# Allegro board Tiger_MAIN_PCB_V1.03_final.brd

Outline 253.3 x 113.9 mm; copper layers: TOP, LAY2, LAY3, LAY4, LAY5, LAY6, LAY7, BOTTOM. Coordinates in mm from the lower left corner of the outline.

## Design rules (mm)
net group +V1.5S: nets +V1.5S AVDD2_AUDIO
net group EDP_TX_DN*: nets EDP_TX_DN*<0> EDP_TX_DN*<1>
net group EDP_TX_DP: nets EDP_TX_DP<0> EDP_TX_DP<1>
net group FLASH_SPI_CLK: nets FLASH_SPI_CLK N26757835
net group FLASH_SPI_D<2>: nets FLASH_SPI_D<2> N26757763
net group FLASH_SPI_D<3>: nets FLASH_SPI_D<3> N26757648
net group FLASH_SPI_MISO: nets FLASH_SPI_MISO N26757791
net group FLASH_SPI_MOSI: nets FLASH_SPI_MOSI N26757807
net group HDA_RST#: nets HDA_RST# N34600535
net group HSON: nets HSON PCIE_RX_DN*<4>
net group HSOP: nets HSOP PCIE_RX_DP<4>
net group I2C_DATA1: nets I2C_DATA1 SMB_L1DATA_PCH
net group LAN_TX0N: nets LAN_TX0N N34595676
net group LAN_TX0P: nets LAN_TX0P N34595663
net group LAN_TX1N: nets LAN_TX1N N34595656
net group LAN_TX1P: nets LAN_TX1P N34595746
net group LAN_TX2N: nets LAN_TX2N N34595569
net group LAN_TX2P: nets LAN_TX2P N34595869
net group LAN_TX3N: nets LAN_TX3N N34595884
net group LAN_TX3P: nets LAN_TX3P N34595477
net group M_B_CLK_DDR<0>: nets M_B_CLK_DDR_DN*<0> M_B_CLK_DDR_DP<0>
net group M_B_CLK_DDR<1>: nets M_B_CLK_DDR_DN*<1> M_B_CLK_DDR_DP<1>
net group M_CLKOUT_SRC_<1>: nets WIFI_PCIE_CLK_DN WIFI_PCIE_CLK_DP
net group M_EDP_AUX_D*: nets EDP_AUX_DN* EDP_AUX_DP
net group M_LAN_PCIE_CLK_D: nets LAN_PCIE_CLK_DN LAN_PCIE_CLK_DP
net group M_LAO1_CLK: nets LAO1_CLKN LAO1_CLKP
net group M_LAO1_DATA0: nets LAO1_DATAN0 LAO1_DATAP0
net group M_LAO1_DATA1: nets LAO1_DATAN1 LAO1_DATAP1
net group M_LAO1_DATA2: nets LAO1_DATAN2 LAO1_DATAP2
net group M_LAO1_DATA3: nets LAO1_DATAN3 LAO1_DATAP3
net group M_LAO_CLK: nets LAO_CLKN LAO_CLKP
net group M_LAO_DATA0: nets LAO_DATAN0 LAO_DATAP0
net group M_LAO_DATA1: nets LAO_DATAN1 LAO_DATAP1
net group M_LAO_DATA2: nets LAO_DATAN2 LAO_DATAP2
net group M_LAO_DATA3: nets LAO_DATAN3 LAO_DATAP3
net group M_MDI0: nets MDI0+ MDI0-
net group M_MDI1: nets MDI1+ MDI1-
net group M_MDI2: nets MDI2+ MDI2-
net group M_MDI3: nets MDI3+ MDI3-
net group M_PCIE_RX_9_SSD: nets PCIE_RX_DN_9_SSD PCIE_RX_DP_9_SSD
net group M_PCIE_RX_10_SSD: nets PCIE_RX_DN_10_SSD PCIE_RX_DP_10_SSD
net group M_PCIE_RX_11_SSD: nets PCIE_RX_DN_11_SSD PCIE_RX_DP_11_SSD
net group M_PCIE_RX_12_SSD: nets PCIE_RX_DN_12_SSD PCIE_RX_DP_12_SSD
net group M_PCIE_RX_12_SSD0: nets N37689443 N37689445
net group M_PCIE_TX_9_SSD: nets PCIE_TX_DN_9_SSD PCIE_TX_DP_9_SSD
net group M_PCIE_TX_9_SSD0: nets N37690406 N37690408
net group M_PCIE_TX_10_SSD: nets PCIE_TX_DN_10_SSD PCIE_TX_DP_10_SSD
net group M_PCIE_TX_10_SSD0: nets N37690460 N37690481
net group M_PCIE_TX_11_SSD: nets PCIE_TX_DN_11_SSD PCIE_TX_DP_11_SSD
net group M_PCIE_TX_11_SSD0: nets N37690514 N37690535
net group M_PCIE_TX_12_SSD: nets PCIE_TX_DN_12_SSD PCIE_TX_DP_12_SSD
net group M_PCIE_TX_12_SSD0: nets N37689471 N37689473
net group M_SSD_PCIE_CLK: nets SSD_PCIE_CLK_DN SSD_PCIE_CLK_DP
net group M_SSD_PCIE_CLK0: nets N37689278 N37689280
net group M_USB2_D22: nets N37310916 N37310979
net group M_USB3_RX_<2>0: nets N37310918 N37310942
net group M_USB3_TX_<2>00: nets N37310944 N37311057
net group MG_FBB_DATA1: nets M_B_DQS_DN*<1> M_B_DQS_DP<1>
net group PCIE_RCOMPN: nets PCIE_RCOMPN PCIE_RCOMPP
net group PCIE_TX_DN*<4>: nets PCIE_TX_C_DN*<4> PCIE_TX_DN*<4>
net group PCIE_TX_DN_1_WIFI: nets PCIE_TX_C_DN_1_WIFI PCIE_TX_DN_1_WIFI
net group PCIE_TX_DP<4>: nets PCIE_TX_C_DP<4> PCIE_TX_DP<4>
net group PCIE_TX_DP_1_WIFI: nets PCIE_TX_C_DP_1_WIFI PCIE_TX_DP_1_WIFI
net group SSD_SATA_RXN1: nets N37458279 SSD_SATA_RXN1
net group SSD_SATA_RXP1: nets N37458304 SSD_SATA_RXP1
net group SSD_SATA_TXN1: nets N37458287 SSD_SATA_TXN1
net group SSD_SATA_TXP1: nets N37458285 SSD_SATA_TXP1
net group USB2_D<10>: nets USB2_DN*<10> USB2_DP<10>
net group USB2_DN*<1>: nets N34544223 USB2_DN*<1>
net group USB2_DN*<4>: nets N37310702 USB2_DN*<4>
net group USB2_DN*<5>: nets N37309832 USB2_DN*<5>
net group USB2_DP<1>: nets N34544176 USB2_DP<1>
net group USB2_DP<4>: nets N37310717 USB2_DP<4>
net group USB2_DP<5>: nets N37309834 USB2_DP<5>
net group USB3_RX_DN*<1>: nets N34544234 USB3_RX_DN*<1>
net group USB3_RX_DP<1>: nets N34544271 USB3_RX_DP<1>
net group USB3_TX_<2>0: nets N37310933 N37310966
net group XDP_BPM: nets XDP_BPM<2> XDP_BPM<3>
net group 50OHM: nets ALL_SYS_PWRGD_VRON CPU_POPIRCOMP CSI2_COMP DRVH1 DRVL1 EC_HID_INT* EC_PCH_RCIN* EDP_BKLEN_OUT EDP_COMP EDP_HPD EDRAM_EDM EDRAM_OPIO_RCOMP EMMC_RCOMP EOPIO_RCOMP EXT_BOOT_STALL_STRAP FAN_VCC ITP_PMODE L_BKLT_EN L_BRIGHTNESS LPC_CLKRUN* LPC_FRAME* MPHY_EXT_PWR_GATE* N26714753 N26739346 N29995527 N30351801 N30362590 N30362889 N30418600 N30418602 N30475256 N30475258 N31079742 N32759666 N32938866 N32938875 N33387416 N33387421 N34176799 NOA_RCOMP PCH_EDM PCH_LPC_CLK1 PCH_PLT_RST* PCH_POPIRCOMP PCH_PWROK PCH_SLP_LAN* PCH_SLP_S5* PCH_SLP_SA* PCH_SLP_WLAN* PCH_SUSACK* PCH_SUSPWRACK* PLT_RST_BUF* PM_CPUPWRGD PM_LANPHY_ENABLE PM_SLP_S3* PM_SUS_STAT* RTC_X1 RTC_X2 SD_RCOMP SM_RCOMP_0 SM_RCOMP_1 SM_RCOMP_2 SOC_CATERR* SOC_THRMTRIP* SW1 TLS_CONFIDENTIALITY WLAN_PCIE_WAKE* XCLK_BIASREF
net group CFG: nets CFG<0> CFG<1> CFG<2> CFG<3> CFG<4> CFG<5> CFG<6> CFG<8> CFG<9> CFG<10> CFG<12> CFG<13>
net group M_DDRB_CMD: nets M_B_A0 M_B_A1 M_B_A2 M_B_A3 M_B_A4 M_B_A5 M_B_A6 M_B_A7 M_B_A8 M_B_A9 M_B_A10 M_B_A11 M_B_A12 M_B_A13 M_B_ACT_N M_B_BG0 M_B_BG1 M_B_BS0 M_B_BS1 M_B_CAS_N M_B_RAS_N M_B_WE_N
net group M_DDRB_CTL_MM: nets M_B_CKE<0> M_B_CKE<1> M_B_CS*<0> M_B_CS*<1> M_B_ODT<0> M_B_ODT<1>
net group M_DDRB_DQS: nets M_B_DQS_DP<0>
net group M_DDRB_DQS0: nets M_B_DQS_DN*<0>
net group M_FLASH_SPI: nets FLASH_SPI_CS*
net group MG_FBB_DATA2: nets M_B_DQ<16> M_B_DQ<17> M_B_DQ<18> M_B_DQ<19> M_B_DQ<20> M_B_DQ<21> M_B_DQ<22> M_B_DQ<23> M_B_DQS_DN*<2> M_B_DQS_DP<2>
net group MG_FBB_DATA3: nets M_B_DQ<24> M_B_DQ<25> M_B_DQ<26> M_B_DQ<27> M_B_DQ<28> M_B_DQ<29> M_B_DQ<30> M_B_DQ<31> M_B_DQS_DN*<3> M_B_DQS_DP<3>
net group MG_FBB_DATA4: nets M_B_DQ<32> M_B_DQ<33> M_B_DQ<34> M_B_DQ<35> M_B_DQ<36> M_B_DQ<37> M_B_DQ<38> M_B_DQ<39> M_B_DQS_DN*<4> M_B_DQS_DP<4>
net group MG_FBB_DATA5: nets M_B_DQ<40> M_B_DQ<41> M_B_DQ<42> M_B_DQ<43> M_B_DQ<44> M_B_DQ<45> M_B_DQ<46> M_B_DQ<47> M_B_DQS_DN*<5> M_B_DQS_DP<5>
net group MG_FBB_DATA6: nets M_B_DQ<48> M_B_DQ<49> M_B_DQ<50> M_B_DQ<51> M_B_DQ<52> M_B_DQ<53> M_B_DQ<54> M_B_DQ<55> M_B_DQS_DN*<6> M_B_DQS_DP<6>
net group MG_FBB_DATA7: nets M_B_DQ<58> M_B_DQ<59> M_B_DQ<60> M_B_DQ<61> M_B_DQ<62> M_B_DQ<63> M_B_DQS_DN*<7> M_B_DQS_DP<7>
net group NET_GND: nets GND
net group PCIE_RX_DN*: nets PCIE_RX_DN_1_WIFI
net group PCIE_RX_DP: nets PCIE_RX_DP_1_WIFI
net group POWER: nets +V1P00A +V1P00S_VCCST +V1P00S_VCCSTG +V1P8A +V1P8A_SIP +V1P8S +V3.3S_MSATA +V3P3_BIOS_SPI +V3P3A +V3P3A_RTC +V3P3A_SIP +V5A +V5S +VCCCORE +VCCDSW_1P0 +VCCGT +VCCPAZIO +VCCPDSW_3P3 +VCCPGPPD +VCCPGPPG +VCCSA +VDDQ_MEM CORE_BOO CORE_FCCM CORE_PWM1 GT_FCCM N36036104 SA_FCCM SA_LG_DRV SA_PWM
net group SMB: nets SMB_CLK SMB_CLK_S2 SMB_DATA SMB_DATA_S2
net group SRC_CLK_REQ*: nets WIFI_CLK_REQ*
net group USB2_DN*: nets USB2_DN*<2> USB2_DN*<3> USB2_DN*<7>
net group USB2_DP: nets USB2_DP<2> USB2_DP<3> USB2_DP<7>
net group USB2_OC*: nets USB2_OC*<0> USB2_OC*<1> USB2_OC*<2> USB2_OC*<3>
net group USB3_RX_DN*: nets USB3_RX_DN*<2>
net group USB3_RX_DP: nets USB3_RX_DP<2>
net group USB3_TX_DN*: nets USB3_TX_DN*<2>
net group USB3_TX_DN*<1>: nets N34544208 N34544244 USB3_TX_DN*<1>
net group USB3_TX_DP: nets USB3_TX_DP<2>
net group USB3_TX_DP<1>: nets N34544097 N34544206 USB3_TX_DP<1>

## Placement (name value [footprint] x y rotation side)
B1  MIC-2_0  [MIC_FOM6050MP3_190P]  57.4 8.1 180 top
C1  20PF  [CC0402N]  207.99 82.8 0 top
C2  20PF  [CC0402N]  206.22 82.8 180 top
C3  1uF  [CC0603N]  177.76 43.69 270 bottom
C4  1uF  [CC0603N]  179.18 43.69 270 bottom
C5  10pF  [CC0402N]  189.22 45.26 0 bottom
C6  10pF  [CC0402N]  187.46 45.26 180 bottom
C7  22nF  [CC0402N]  227.17 44.57 180 bottom
C8  22nF  [CC0402N]  227.17 46.9 180 bottom
C9  100nF  [CC0402N]  196.11 83.57 90 top
C10  100nF  [CC0402N]  195.28 83.57 90 top
C11  100nF  [CC0402N]  196.99 83.57 90 top
C12  100nF  [CC0402N]  197.76 83.56 90 top
C13  0.1u  [CC0402N]  190.59 52.43 0 bottom
C14  10uF  [CC1210N]  159.09 82.19 270 top
C15  47UF  [CC0805N]  192.84 90.81 270 bottom
C16  47UF  [CC0805N]  190.28 89.86 180 bottom
C17  47UF  [CC0805N]  195.91 89.85 180 bottom
C18  47UF  [CC0805N]  205.74 91.34 90 bottom
C19  47UF  [CC0805N]  195.4 95.98 90 bottom
C20  47UF  [CC0805N]  211.32 88.75 90 bottom
C21  47UF  [CC0805N]  209.63 88.76 90 bottom
C22  47UF  [CC0805N]  190.28 91.58 180 bottom
C23  22uF  [CC0603N]  203.66 93.46 90 bottom
C24  22uF  [CC0603N]  209.12 68.71 270 bottom
C25  22uF  [CC0603N]  205.87 68.72 270 bottom
C26  22uF  [CC0603N]  208.17 88.95 90 bottom
C27  22uF  [CC0603N]  197.06 95.78 90 bottom
C28  22uF  [CC0603N]  201.73 86.98 0 top
C29  22uF  [CC0603N]  192.5 88.42 0 bottom
C30  22uF  [CC0603N]  201.73 85.76 0 top
C31  22uF  [CC0603N]  195.57 88.42 180 bottom
C32  10uF  [CC0402N]  206.1 80.49 270 top
C33  10uF  [CC0402N]  208.58 80.49 270 top
C34  10uF  [CC0402N]  204.75 80.49 270 top
C35  10uF  [CC0402N]  201.27 84.75 180 top
C36  10uF  [CC0402N]  201.27 83.94 180 top
C37  10uF  [CC0402N]  201.27 83.06 180 top
C38  10uF  [CC0402N]  203.27 84.82 0 bottom
C39  10uF  [CC0402N]  201.27 84.75 180 bottom
C40  10uF  [CC0402N]  201.27 83.87 180 bottom
C41  10uF  [CC0402N]  201.27 83 180 bottom
C42  10uF  [CC0402N]  203.29 84.75 0 top
C43  10uF  [CC0402N]  203.27 83.93 0 top
C44  10uF  [CC0402N]  203.27 83.02 0 top
C45  10uF  [CC0402N]  203.27 83.02 0 bottom
C46  10uF  [CC0402N]  203.27 83.91 0 bottom
C47  1uF  [CC0201N]  205.37 63.76 90 bottom
C48  1uF  [CC0201N]  206.07 63.75 90 bottom
C49  1uF  [CC0201N]  207.91 63.72 90 bottom
C50  1uF  [CC0201N]  209.66 63.75 90 bottom
C51  1uF  [CC0201N]  208.46 66.25 0 bottom
C52  1uF  [CC0201N]  206.5 66.96 180 bottom
C53  1uF  [CC0201N]  210.43 70.78 270 bottom
C54  1uF  [CC0201N]  209.37 72.63 90 bottom
C55  1uF  [CC0201N]  207.44 72.59 270 bottom
C56  1uF  [CC0201N]  206.61 72.59 270 bottom
C57  1uF  [CC0201N]  205.61 72.59 270 bottom
C58  1uF  [CC0201N]  204.28 70.76 270 bottom
C59  1uF  [CC0201N]  205.29 66.95 0 bottom
C60  1uF  [CC0201N]  209.65 66.87 180 bottom
C61  1uF  [CC0201N]  209.66 65.62 180 bottom
C62  1uF  [CC0201N]  210.27 63.75 90 bottom
C63  1uF  [CC0201N]  205.94 61.58 90 bottom
C64  1uF  [CC0201N]  207.29 61.46 90 bottom
C65  1uF  [CC0201N]  207.13 63.75 90 bottom
C66  1uF  [CC0201N]  208.89 63.75 90 bottom
C67  1uF  [CC0201N]  209.66 66.25 180 bottom
C68  1uF  [CC0201N]  210.18 72.62 90 bottom
C69  1uF  [CC0201N]  208.46 65.61 0 bottom
C70  1uF  [CC0201N]  207.9 61.46 90 bottom
C71  1uF  [CC0201N]  208.42 66.88 0 bottom
C72  1uF  [CC0201N]  206.5 66.25 180 bottom
C73  1uF  [CC0201N]  205.31 66.25 0 bottom
C74  1uF  [CC0201N]  208.81 70.77 270 bottom
C75  1uF  [CC0201N]  207.92 70.76 270 bottom
C76  1uF  [CC0201N]  207.12 70.76 270 bottom
C77  1uF  [CC0201N]  206.2 70.75 270 bottom
C78  1uF  [CC0201N]  205.21 70.74 270 bottom
C79  1uF  [CC0201N]  209.6 70.78 270 bottom
C80  1uF  [CC0201N]  208.35 72.62 90 bottom
C81  1uF  [CC0201N]  204.11 72.84 180 bottom
C82  47UF  [CC0805N]  214.81 87.37 180 top
C83  47UF  [CC0805N]  214.82 89.01 180 top
C84  47UF  [CC0805N]  214.83 85.69 180 top
C85  47UF  [CC0805N]  224.25 88.24 0 top
C86  47UF  [CC0805N]  224.25 89.86 0 top
C87  22uF  [CC0603N]  233.33 70.88 90 top
C88  22uF  [CC0603N]  231.81 70.88 90 top
C89  22uF  [CC0603N]  227.37 88.76 180 bottom
C90  22uF  [CC0603N]  224.46 87.49 0 bottom
C91  22uF  [CC0603N]  227.39 87.49 180 bottom
C92  22uF  [CC0603N]  224.5 90.04 0 bottom
C93  22uF  [CC0603N]  224.46 88.76 0 bottom
C94  10uF  [CC0402N]  220.6 51.93 90 bottom
C95  10uF  [CC0402N]  219.82 51.93 90 bottom
C96  10uF  [CC0402N]  219.04 51.93 90 bottom
C97  10uF  [CC0402N]  238.85 72.92 180 top
C98  10uF  [CC0402N]  238.84 72.13 180 top
C99  10uF  [CC0402N]  238.84 67.36 180 top
C100  10uF  [CC0402N]  238.85 71.35 180 top
C101  10uF  [CC0402N]  231.61 66.52 90 top
C102  10uF  [CC0402N]  236.47 66.46 90 top
C103  10uF  [CC0402N]  218.39 72.87 0 bottom
C104  10uF  [CC0402N]  219.47 70.64 0 bottom
C105  10uF  [CC0402N]  220.19 72.85 180 bottom
C106  1uF  [CC0201N]  221.55 66.18 270 bottom
C107  1uF  [CC0201N]  232.15 65.71 90 bottom
C108  1uF  [CC0201N]  232.87 65.71 90 bottom
C109  1uF  [CC0201N]  231.49 65.71 90 bottom
C110  1uF  [CC0201N]  230.78 65.71 90 bottom
C111  1uF  [CC0201N]  213.34 69.63 90 bottom
C112  1uF  [CC0201N]  225.14 80.97 180 bottom
C113  1uF  [CC0201N]  219.42 69.65 90 bottom
C114  1uF  [CC0201N]  219.43 67.73 90 bottom
C115  1uF  [CC0201N]  212.57 70.85 270 bottom
C116  1uF  [CC0201N]  213.34 70.85 270 bottom
C117  1uF  [CC0201N]  221.54 65 90 bottom
C118  1uF  [CC0201N]  220.72 65 90 bottom
C119  1uF  [CC0201N]  220.73 66.18 270 bottom
C120  10uF  [CC0402N]  236.39 71.33 270 top
C121  10uF  [CC0402N]  235.59 71.33 270 top
C122  10uF  [CC0402N]  234.78 71.33 270 top
C123  10uF  [CC0402N]  212.1 72.84 0 bottom
C124  10uF  [CC0402N]  232.41 66.52 90 top
C125  10uF  [CC0402N]  235.69 66.46 90 top
C126  10uF  [CC0402N]  227.4 89.8 0 bottom
C127  10uF  [CC0402N]  221.76 67.66 270 bottom
C128  10uF  [CC0402N]  217.97 63.71 0 bottom
C129  10uF  [CC0402N]  216.06 63.71 180 bottom
C130  10uF  [CC0402N]  214.16 63.71 0 bottom
C131  10uF  [CC0402N]  212.25 63.71 180 bottom
C132  10uF  [CC0402N]  233.19 66.52 90 top
C133  10uF  [CC0402N]  234.91 66.46 90 top
C134  10uF  [CC0402N]  215.74 72.88 180 bottom
C135  10uF  [CC0402N]  221 67.66 270 bottom
C136  10uF  [CC0402N]  222.21 51.91 90 bottom
C137  10uF  [CC0402N]  221.42 51.92 90 bottom
C138  10uF  [CC0402N]  218.21 51.93 90 bottom
C139  10uF  [CC0402N]  238.84 68.97 180 top
C140  10uF  [CC0402N]  238.84 69.76 180 top
C141  10uF  [CC0402N]  238.84 70.58 180 top
C142  10uF  [CC0402N]  225.15 83.97 0 bottom
C143  10uF  [CC0402N]  217.39 51.93 90 bottom
C144  10uF  [CC0402N]  238.84 68.16 180 top
C145  10uF  [CC0402N]  225.19 81.77 0 bottom
C146  10uF  [CC0402N]  220.29 61.4 180 bottom
C147  10uF  [CC0402N]  218.46 61.43 0 bottom
C148  10uF  [CC0402N]  216.56 61.43 180 bottom
C149  10uF  [CC0402N]  214.65 61.43 0 bottom
C150  1uF  [CC0201N]  231.54 66.86 270 bottom
C151  1uF  [CC0201N]  233.27 71.31 90 bottom
C152  1uF  [CC0201N]  232.65 71.31 90 bottom
C153  1uF  [CC0201N]  232.04 71.31 90 bottom
C154  1uF  [CC0201N]  232.88 66.86 270 bottom
C155  1uF  [CC0201N]  232.16 66.86 270 bottom
C156  1uF  [CC0201N]  217.87 69.63 90 bottom
C157  1uF  [CC0201N]  215.27 69.63 90 bottom
C158  1uF  [CC0201N]  217.08 69.63 90 bottom
C159  1uF  [CC0201N]  216.09 69.63 90 bottom
C160  1uF  [CC0201N]  214.19 69.63 90 bottom
C161  1uF  [CC0201N]  217.84 70.83 270 bottom
C162  1uF  [CC0201N]  217.08 70.83 270 bottom
C163  1uF  [CC0201N]  216.04 70.84 270 bottom
C164  1uF  [CC0201N]  215.28 70.84 270 bottom
C165  1uF  [CC0201N]  214.1 70.85 270 bottom
C166  1uF  [CC0201N]  212.72 69.63 90 bottom
C167  1uF  [CC0201N]  231.43 71.3 90 bottom
C168  1uF  [CC0201N]  230.83 71.3 90 bottom
C169  1uF  [CC0201N]  230.82 66.86 270 bottom
C170  10uF  [CC0402N]  209.06 52.23 0 bottom
C171  10uF  [CC0402N]  198.89 52.31 90 top
C172  10uF  [CC0402N]  205.1 52.35 180 bottom
C173  10uF  [CC0402N]  213.06 52.46 90 top
C174  10uF  [CC0402N]  204.11 52.35 90 top
C175  10uF  [CC0402N]  209.46 52.16 90 top
C176  1uF  [CC0201N]  202.85 61.81 90 bottom
C177  1uF  [CC0201N]  201.96 61.98 90 bottom
C178  1uF  [CC0201N]  202.2 63.47 180 bottom
C179  1uF  [CC0201N]  204.51 61.35 0 bottom
C180  1uF  [CC0201N]  201.09 61.99 90 bottom
C181  1uF  [CC0201N]  210 60.77 180 bottom
C182  1uF  [CC0201N]  204.13 61.96 0 bottom
C183  10uF  [CC0402N]  169.34 56.74 0 top
C184  10uF  [CC0402N]  169.34 57.58 0 top
C185  1uF  [CC0201N]  203.35 52.42 0 bottom
C186  1uF  [CC0201N]  213.29 52.36 0 bottom
C187  22uF  [CC0603N]  216.18 45.29 0 bottom
C188  22uF  [CC0603N]  216.18 43.98 0 bottom
C189  22uF  [CC0603N]  216.18 42.7 0 bottom
C190  1uF  [CC0201N]  203.36 63.29 0 bottom
C191  1uF  [CC0201N]  208.64 60.22 180 bottom
C192  1uF  [CC0201N]  213.29 51.75 0 bottom
C193  10uF  [CC0402N]  170.94 91.63 0 bottom
C194  10uF  [CC0402N]  183.34 85.38 270 bottom
C195  10uF  [CC0402N]  181.65 86.98 180 bottom
C196  10uF  [CC0402N]  181.65 86.05 180 bottom
C197  10uF  [CC0402N]  170.92 89.07 0 bottom
C198  10uF  [CC0402N]  170.94 89.92 0 bottom
C199  47UF  [CC0805N]  178.08 89.62 0 top
C200  1uF  [CC0201N]  208.78 61.74 180 bottom
C201  10uF  [CC0402N]  211.11 61.87 180 bottom
C202  10uF  [CC0402N]  181.65 87.83 180 bottom
C203  10uF  [CC0402N]  180.13 88.84 180 bottom
C204  10uF  [CC0402N]  184.16 85.38 270 bottom
C205  10uF  [CC0402N]  185.37 85.37 270 bottom
C206  10uF  [CC0402N]  186.15 85.38 270 bottom
C207  10uF  [CC0402N]  170.94 90.8 0 bottom
C208  1uF  [CC0402N]  195.92 80.49 270 top
C209  1uF  [CC0201N]  202.86 72.93 0 bottom
C210  1uF  [CC0201N]  200.18 72.95 180 bottom
C211  1uF  [CC0201N]  203.02 68.76 90 bottom
C212  1uF  [CC0201N]  200.58 68.77 90 bottom
C213  1uF  [CC0201N]  203.01 70.62 270 bottom
C214  1uF  [CC0201N]  200.58 70.56 270 bottom
C215  1uF  [CC0201N]  202.64 64.3 0 bottom
C216  1uF  [CC0402N]  198.68 81.16 270 top
C217  1uF  [CC0402N]  213.5 49.96 180 bottom
C218  1uF  [CC0402N]  199.15 72.22 180 bottom
C219  1uF  [CC0402N]  199.57 70.77 90 bottom
C220  1uF  [CC0402N]  182.75 64.4 90 bottom
C221  1uF  [CC0402N]  184.61 50.1 180 bottom
C222  0.1u  [CC0402N]  184.61 51.02 180 bottom
C223  0.1u  [CC0402N]  184.61 51.89 180 bottom
C224  1uF  [CC0402N]  199.42 68.5 270 bottom
C225  1uF  [CC0402N]  178.9 62.33 180 top
C226  1uF  [CC0402N]  170.98 61.79 0 bottom
C227  47UF  [CC0805N]  175.63 71.41 270 bottom
C228  1uF  [CC0402N]  184.01 61.37 180 top
C229  1uF  [CC0402N]  171.02 64.11 0 bottom
C230  1uF  [CC0402N]  184.06 72.03 0 top
C231  1uF  [CC0402N]  184.13 66.81 0 top
C232  1uF  [CC0402N]  176.86 71.2 90 bottom
C233  1uF  [CC0402N]  194.43 52.22 180 bottom
C234  47UF  [CC0805N]  181.85 83.38 90 top
C235  22uF  [CC0603N]  181.9 47.23 180 bottom
C236  22uF  [CC0603N]  181.92 45.97 180 bottom
C237  47UF  [CC0805N]  183.57 83.38 90 top
C238  47UF  [CC0805N]  185.2 83.38 90 top
C239  1uF  [CC0402N]  198.11 69.06 180 bottom
C240  1uF  [CC0402N]  191.86 80.27 270 top
C241  1uF  [CC0402N]  196.36 70.48 270 bottom
C242  47UF  [CC0805N]  180.05 83.39 90 top
C243  47UF  [CC0805N]  175.88 67.34 180 bottom
C244  1uF  [CC0402N]  196.28 52.2 0 bottom
C245  1uF  [CC0402N]  198.34 51.48 90 bottom
C248  100nF  [CC0402N]  168.07 22.71 270 top
C249  2.2uF  [CC0603N]  167.06 22.99 270 top
C250  100nF  [CC0402N]  194 18.11 270 bottom
C264  1000pF  [CC0402N]  104.78 91.14 180 bottom
C274  22nF  [CC0402N]  228.85 49.79 90 top
C281  100nF  [CC0402N]  146.31 85.6 180 bottom
C282  100NF  [CC0402N]  241.24 73.4 270 top
C283  10uF  [CC0603N]  184.83 24.91 270 bottom
C284  0.1u  [CC0402N]  187.14 24.84 270 bottom
C285  100nF  [CC0402N]  76.76 35.61 0 bottom
C286  10uF  [CC0603N]  76.33 54.89 90 bottom
C287  10uF  [CC0805N]  74.26 55.01 270 bottom
C292  100nF  [CC0402N]  77.36 54.88 270 bottom
C293  0.22uF  [CC0603N]  241.19 82.63 270 bottom
C294  0.01uF  [CC0402N]  233.15 95.97 180 bottom
C295  1800PF  [CC0402N]  231.85 93.07 270 bottom
C296  0.1uF  [CC0402N]  231.61 96.98 180 bottom
C297  0.01uF  [CC0402N]  233.15 94.75 180 bottom
C298  10uF  [CC1210N]  98.42 95.77 90 bottom
C299  0.012uF  [CC0603N]  242.53 99.35 0 bottom
C300  68pF  [CC0402N]  232.41 89.12 0 bottom
C301  8200pF  [CC0402N]  231.85 91.19 180 bottom
C302  680pF  [CC0402N]  234.94 85.42 270 top
C303  3900pF  [CC0402N]  242.35 96.45 90 bottom
C304  0.1uF  [CC0402N]  243.64 96.93 0 bottom
C305  0.33 nF  [CC0402N]  237.94 100.92 0 bottom
C306  0.33 nF  [CC0402N]  238.71 83.69 180 top
C307  0.082uF  [CC0603N]  243.14 98.14 180 bottom
C308  270pF  [CC0402N]  232.82 87.33 0 bottom
C309  1.0 nF  [CC0402N]  237.39 98.18 90 bottom
C310  47UF  [CC0805N]  178.59 92.45 0 bottom
C311  0.022uF  [CC0402N]  246.31 84.06 90 bottom
C312  68pF  [CC0402N]  244.94 91.54 0 bottom
C313  8200pF  [CC0402N]  244.94 92.34 0 bottom
C314  470PF  [CC0402N]  240.24 100.44 90 bottom
C315  0.1uF  [CC0402N]  245.84 85.34 0 bottom
C316  330pF  [CC0402N]  236.12 94.14 90 bottom
C317  0.33 nF  [CC0402N]  239.97 94.93 180 bottom
C318  2.2nF  [CC0402N]  246.29 95.96 270 bottom
C319  330pF  [CC0402N]  244.94 93.93 0 bottom
C320  0.01uF  [CC0402N]  244.58 86.71 90 bottom
C321  4.7uF  [CC0603N]  175.78 95.24 180 bottom
C322  220nF  [CC0402N]  89.57 50.84 180 top
C323  4.7uF  [CC0603N]  207.55 95.36 270 bottom
C324  0.33 nF  [CC0402N]  235.46 82.46 180 top
C325  4.7uF  [CC0603N]  158.74 85.32 270 bottom
C326  220nF  [CC0402N]  89.57 50.06 180 top
C327  220nF  [CC0402N]  199.45 80.31 90 top
C328  10uF  [CC0603N]  233.01 39.19 180 bottom
C329  10uF  [CC0603N]  238.28 30.16 0 bottom
C330  220nF  [CC0402N]  200.23 80.31 90 top
C331  220nF  [CC0402N]  202.31 80.26 90 top
C332  220nF  [CC0402N]  201.46 80.25 90 top
C333  220nF  [CC0402N]  89.5 41.67 0 top
C334  0.1u  [CC0402N]  238.24 52.5 90 top
C338  220nF  [CC0402N]  89.5 40.88 0 top
C339  10uF  [CC0603N]  157.56 57.44 0 bottom
C340  0.1u  [CC0402N]  157.46 58.46 0 bottom
C341  0.1u  [CC0402N]  152.36 47.07 180 bottom
C343  10uF  [CC0603N]  152.45 46.06 180 bottom
C344  0.1u  [CC0402N]  162.58 41.82 180 top
C368  0.1uF  [CC0603N]  135.51 18.06 90 bottom
C369  0.1uF  [CC0603N]  136.76 18.06 90 bottom
C371  20PF  [CC0402N]  123.16 34.6 270 bottom
C372  20PF  [CC0402N]  124.35 34.6 270 bottom
C373  0.1u  [CC0402N]  113.32 48.99 90 bottom
C374  0.01uF  [CC0402N]  112.53 44.91 90 bottom
C375  10uF  [CC0805N]  117.98 48.4 90 bottom
C376  10uF  [CC0603N]  112.26 49.03 90 bottom
C377  0.1u  [CC0402N]  130.79 43.46 45 bottom
C378  0.1u  [CC0402N]  131.34 37.4 270 bottom
C379  0.1u  [CC0402N]  125.41 34.66 270 bottom
C380  0.1u  [CC0402N]  127.65 33.67 270 bottom
C381  0.1u  [CC0402N]  121.37 36.65 180 bottom
C382  10uF  [CC0603N]  119.45 48.31 90 bottom
C383  4.7uF  [CC0603N]  132.83 36.82 90 bottom
C384  0.1u  [CC0402N]  121.37 37.45 180 bottom
C385  4.7uF  [CC0603N]  129.83 29.62 90 bottom
C386  0.1u  [CC0402N]  128.97 46.73 225 bottom
C387  0.1u  [CC0402N]  130.86 41.85 45 bottom
C388  0.1u  [CC0402N]  127.46 45.03 45 bottom
C389  0.1u  [CC0402N]  126.57 34.66 270 bottom
C390  0.1u  [CC0402N]  122.27 34.02 270 bottom
C391  0.1u  [CC0402N]  120.71 38.81 180 bottom
C392  0.1u  [CC0402N]  120.69 40.3 180 bottom
C393  0.1u  [CC0402N]  120.79 41.79 180 bottom
C394  0.1u  [CC0402N]  129.72 45.29 225 bottom
C395  0.1u  [CC0402N]  129.18 45.84 225 bottom
C396  1uF  [CC0402N]  128.81 29.79 90 bottom
C397  0.1u  [CC0402N]  122.84 44.95 90 bottom
C398  0.01uF  [CC0402N]  116.5 30.57 90 top
C399  0.1u  [CC0402N]  102.65 30.18 180 top
C400  0.01uF  [CC0402N]  102.64 28.63 0 top
C401  1000pF  [CC1206N]  102.49 27.08 0 top
C402  1000pF  [CC0402N]  102.65 29.4 180 top
C403  0.01uF  [CC0402N]  79.97 18.64 180 top
C404  1000pF  [CC0402N]  79.97 17.84 180 top
C405  10uF  [CC1206N]  26.57 83.42 90 bottom
C406  0.1u  [CC0402N]  25.16 84.28 90 bottom
C407  10uF  [CC1206N]  10.74 90.77 0 bottom
C408  10uF  [CC1206N]  10.71 88.7 0 bottom
C409  1000pF  [CC0402N]  10.77 92.24 180 bottom
C410  0.1u  [CC0402N]  23.77 90.18 90 bottom
C411  100nF  [CC0402N]  19.01 91.04 0 top
C412  100nF  [CC0402N]  19.01 92.04 0 top
C413  100pF  [CC0402N]  30.61 20.09 0 bottom
C414  100pF  [CC0402N]  37.31 20.09 0 bottom
C416  2.2uF  [CC0603N]  192.96 18.55 270 bottom
C417  100nF  [CC0402N]  215.17 14.43 180 bottom
C418  100pF  [CC0402N]  30.04 31 0 top
C419  100pF  [CC0402N]  26.27 25.33 270 top
C421  100pF  [CC0402N]  23.68 25.85 180 top
C422  100pF  [CC0402N]  24.43 27.17 90 top
C424  10uF  [CC0805N]  10.43 31.17 0 bottom
C425  1uF  [CC0603N]  10.53 29.71 180 bottom
C426  10uF  [CC0805N]  4.28 12.87 0 bottom
C427  1uF  [CC0603N]  4.11 11.43 180 bottom
C428  4.7uF  [CC0603N]  9.05 16.84 180 bottom
C429  10uF  [CC0603N]  5.34 25.25 180 bottom
C430  1uF  [CC0603N]  5 26.74 0 bottom
C431  100nF  [CC0402N]  23.18 17.29 180 bottom
C432  100nF  [CC0402N]  8.9 17.86 0 bottom
C433  2.2uF  [CC0603N]  6.28 22.6 90 bottom
C434  10uF  [CC0603N]  8.6 22.27 0 bottom
C435  100nF  [CC0402N]  9.07 21.28 0 bottom
C436  10uF  [CC0603N]  9.05 15.6 180 bottom
C439  100nF  [CC0402N]  8.43 13.15 180 bottom
C440  10uF  [CC0805N]  8.35 11.94 0 bottom
C441  100nF  [CC0402N]  12.15 24.58 270 bottom
C442  10uF  [CC0603N]  11.12 24.97 90 bottom
C443  2.2uF  [CC0603N]  8.48 23.48 180 bottom
C444  10uF  [CC0603N]  8.48 24.69 0 bottom
C445  2.2uF  [CC0603N]  12.93 13.56 90 bottom
C446  2.2uF  [CC0603N]  11.71 13.56 90 bottom
C447  100nF  [CC0402N]  13.57 25.19 180 bottom
C448  10uF  [CC0805N]  13.52 27.37 90 bottom
C449  100nF  [CC0402N]  15.67 25.19 0 bottom
C450  10uF  [CC0805N]  15.48 27.36 90 bottom
C451  10uF  [CC0603N]  18.61 23.85 90 bottom
C452  100nF  [CC0402N]  17.6 23.4 270 bottom
C453  10uF  [CC0603N]  20.11 19.25 180 bottom
C454  100nF  [CC0402N]  19.13 16.81 90 bottom
C455  22pF  [CC0402N]  21.58 20.59 0 bottom
C456  22pF  [CC0402N]  20.45 13.51 180 bottom
C457  22pF  [CC0402N]  21.41 18.19 180 bottom
C458  22pF  [CC0402N]  19.61 20.61 180 bottom
C459  100nF  [CC0402N]  17.34 29.03 0 bottom
C461  2.2uF  [CC0805N]  112.27 27.41 0 top
C463  10uF  [CC0603N]  138.58 31.47 270 bottom
C464  0.1u  [CC0402N]  139.57 38 180 bottom
C469  10uF  [CC0603N]  139.82 39.05 0 bottom
C470  0.01uF  [CC0402N]  136.94 37.98 180 bottom
C477  10uF  [CC0603N]  38.32 57.09 90 bottom
C479  10uF  [CC0603N]  39.64 57.09 90 bottom
C480  0.1u  [CC0402N]  44.2 61.47 180 bottom
C481  1uF  [CC0402N]  62.24 63.94 90 top
C482  10pF  [CC0402N]  63.07 74.53 90 bottom
C483  0.1u  [CC0402N]  63.77 65.83 0 bottom
C484  10pF  [CC0402N]  63.07 72.7 270 bottom
C485  100nF  [CC0402N]  39.66 63.41 180 bottom
C486  0.1u  [CC0402N]  46.53 60.83 180 top
C487  47pF  [CC0402N]  37.93 61.56 90 bottom
C488  10uF  [CC0603N]  125.17 82.18 180 bottom
C489  1uF  [CC0603N]  125.17 83.46 180 bottom
C490  0.01uF  [CC0402N]  129.24 81.08 90 bottom
C491  10uF  [CC0603N]  125.16 86.13 180 bottom
C495  0.1u  [CC0402N]  125.36 87.14 0 bottom
C510  0.1u  [CC0402N]  132.8 81.08 180 top
C511  10uF  [CC0603N]  173.4 26.32 90 bottom
C512  0.1u  [CC0402N]  175.79 27.33 180 bottom
C513  10uF  [CC0603N]  186.12 24.93 270 bottom
C523  10uF  [CC0603N]  177.55 21.83 270 bottom
C535  4.7uF  [CC0603N]  143.86 26.63 180 bottom
C563  10uF  [CC0603N]  147.5 58.4 90 top
C564  0.1u  [CC0402N]  146.23 58.02 90 top
C565  10uF  [CC0603N]  148.96 51.5 90 top
C566  0.1u  [CC0402N]  149.99 51.62 90 top
C603  10uF  [CC1210N]  116.08 88.8 180 bottom
C607  0.1uF  [CC0603N]  121.35 91.2 180 bottom
C608  0.1u  [CC0402N]  159.36 17.75 90 top
C609  0.1u  [CC0402N]  163.64 20.79 0 top
C610  1000pF  [CC0402N]  160.02 14.41 180 top
C633  4.7uF  [CC0603N]  155.77 48.36 270 top
C634  4.7uF  [CC0603N]  158.23 48.37 270 top
C635  4.7uF  [CC0603N]  157.01 48.36 270 top
C640  10uF  [CC0603N]  210.73 16.98 90 bottom
C641  10uF  [CC0603N]  204.82 15.8 270 bottom
C642  10uF  [CC0603N]  196.92 16.07 270 bottom
C643  10uF  [CC0603N]  202.07 17.1 270 bottom
C644  10uF  [CC0603N]  195.71 20.65 90 bottom
C645  10uF  [CC0603N]  201.8 20.52 90 bottom
C646  10uF  [CC0603N]  211.21 20.72 90 bottom
C648  4.7uF  [CC0603N]  27.33 82.32 270 top
C649  4.7uF  [CC0603N]  26.05 82.34 270 top
C650  10uF  [CC0603N]  206.6 20.57 90 bottom
C651  1uF  [CC0402N]  198.56 20.06 90 bottom
C652  1uF  [CC0402N]  209.48 20.31 90 bottom
C653  1uF  [CC0402N]  203.6 20.42 90 bottom
C654  1uF  [CC0402N]  209.03 15.3 270 bottom
C655  1uF  [CC0402N]  207.86 15.56 270 bottom
C656  1uF  [CC0402N]  200.36 16.81 270 bottom
C657  1uF  [CC0402N]  205.21 20.38 90 bottom
C658  1uF  [CC0402N]  203.34 15.89 270 bottom
C659  10uF  [CC0603N]  176.75 10.3 90 top
C660  1000pF  [CC0402N]  64.73 17.41 90 top
C661  100nF  [CC0402N]  58.13 15.47 270 top
C662  100nF  [CC0402N]  174.83 10.58 90 top
C663  100nF  [CC0402N]  175.64 10.58 90 top
C664  100nF  [CC0402N]  173.24 10.58 90 top
C665  100nF  [CC0402N]  174.03 10.58 90 top
C669  470pF  [CC0402N]  243.44 72.39 0 top
C671  4.7uF  [CC0603N]  11.89 83.76 180 top
C673  4.7uF  [CC0603N]  15.57 80.89 270 top
C678  10uF  [CC0603N]  176.14 21.83 270 bottom
C679  1uF  [CC0402N]  174.18 22.01 90 bottom
C680  1uF  [CC0402N]  175 22 90 bottom
C685  1uF  [CC0402N]  171.05 82.74 270 top
C686  1uF  [CC0402N]  170.18 62.7 180 top
C687  0.1u  [CC0402N]  178.74 84.45 270 top
C688  100nF  [CC0402N]  167.9 58.18 90 top
C689  0.01uF  [CC0402N]  167.66 60.62 90 top
C690  1uF  [CC0402N]  169.23 58.4 0 top
C693  0.1uF  [CC0603N]  233.94 34.14 180 bottom
C694  4.7uF  [CC0603N]  238.28 31.75 0 bottom
C695  4.7uF  [CC0603N]  233.94 32.9 180 bottom
C696  1uF  [CC0603N]  242.34 38.92 180 bottom
C697  0.1uF  [CC0603N]  233.5 35.37 180 bottom
C698  0.1u  [CC0402N]  231.75 36.21 90 bottom
C699  10uF  [CC0603N]  233.02 37.91 180 bottom
C700  0.1u  [CC0402N]  159.88 61.6 270 bottom
C701  1uF  [CC0402N]  157.47 59.26 180 bottom
C702  0.01uF  [CC0402N]  157.48 62.24 180 bottom
C703  0.033uF  [CC0603N]  233.93 43.42 270 bottom
C704  0.01uF  [CC0402N]  235.46 42.37 180 bottom
C705  10uF  [CC0603N]  63.15 11.67 0 top
C706  10uF  [CC0603N]  15.63 60.18 270 top
C707  1000pF  [CC0402N]  37.41 92.08 180 bottom
C708  0.01uF  [CC0402N]  21.83 58.51 90 top
C709  1uF  [CC0402N]  160.72 60.82 270 bottom
C710  100nF  [CC0402N]  47.68 92.41 90 bottom
C711  10uF  [CC0603N]  52.03 86.19 270 bottom
C712  1000pF  [CC0402N]  49.11 16.74 270 top
C713  100nF  [CC0402N]  43 22.47 180 top
C714  10uF  [CC0603N]  40.4 16.93 180 top
C715  10uF  [CC0603N]  37.28 91.04 180 bottom
C716  1uF  [CC0402N]  238.6 84.55 0 bottom
C717  680pF  [CC0402N]  235.46 81.68 0 top
C718  330pF  [CC0402N]  247.08 95.96 90 bottom
C719  1.0 nF  [CC0402N]  239.46 100.43 90 bottom
C720  4.7nF  [CC0402N]  231.51 85.57 180 bottom
C721  0.22uF  [CC0603N]  182.41 97.2 0 bottom
C722  68pF  [CC0402N]  238.19 96.34 90 bottom
C723  1UF  [CC0603N]  174.22 97.02 270 top
C724  4.7uF  [CC0603N]  176.14 101.9 90 top
C725  4.7uF  [CC0603N]  174.88 101.9 90 top
C726  10uF  [CC0603N]  40.56 91.06 0 bottom
C727  4.7uF  [CC0603N]  172.36 102.29 90 top
C728  4.7uF  [CC0603N]  173.62 101.91 90 top
C729  10uF  [CC0603N]  48.11 16.55 270 top
C730  4.7uF  [CC0603N]  209.6 103.36 90 bottom
C731  4.7uF  [CC0603N]  210.81 103.37 90 bottom
C732  1UF  [CC0603N]  213.25 102.75 90 top
C733  4.7uF  [CC0603N]  215.24 102.62 0 top
C734  4.7uF  [CC0603N]  215.25 101.35 0 top
C735  1UF  [CC0603N]  161.3 83.05 270 top
C736  4.7uF  [CC0603N]  158.81 83.05 270 top
C737  4.7uF  [CC0603N]  160.08 83.05 270 top
C738  0.22uF  [CC0603N]  214.02 96.83 180 bottom
C739  10uF  [CC0603N]  46.89 16.57 270 top
C740  0.22uF  [CC0603N]  163.36 90.94 270 bottom
C741  10uF  [CC0603N]  63.66 17.27 90 top
C742  10uF  [CC0603N]  63.66 14.52 270 top
C746  0.1u  [CC0402N]  172.79 48.09 270 top
C747  0.1u  [CC0402N]  171.99 48.08 270 top
C758  1uF  [CC0402N]  159.78 46.88 0 top
C759  0.1uF  [CC0402N]  166.35 70.81 90 top
C761  1uF  [CC0402N]  167.17 45.39 180 top
C767  0.1u  [CC0402N]  18.79 71.83 270 bottom
C768  2.2uF  [CC0603N]  13.57 60.54 270 top
C770  0.1u  [CC0402N]  24.94 67.66 0 bottom
C771  0.1u  [CC0402N]  14.59 60.42 270 top
C772  0.1u  [CC0402N]  32.64 74.25 0 top
C773  1uF  [CC0603N]  16.99 75.71 270 bottom
C774  1uF  [CC0603N]  17.48 67.49 270 bottom
C775  0.1uF  [CC0603N]  15.18 75.68 270 bottom
C776  1UF  [CC0603N]  21.29 64.26 90 bottom
C777  2.2uF  [CC0603N]  32.77 73.12 0 top
C778  0.1u  [CC0402N]  27.12 70.99 0 bottom
C779  0.1u  [CC0402N]  23.11 67.65 180 bottom
C780  0.1u  [CC0402N]  12.92 71.81 90 bottom
C781  0.1u  [CC0402N]  26.58 69.56 90 bottom
C782  4.7uF  [CC0603N]  143.88 27.85 180 bottom
C784  0.1uF  [CC0603N]  141.88 14.03 270 bottom
C785  0.1uF  [CC0603N]  141.88 16.77 270 bottom
C786  0.1uF  [CC0603N]  143.87 25.4 0 bottom
C787  0.1uF  [CC0603N]  138.09 18.09 90 bottom
C790  0.01uF  [CC0402N]  28.56 61.1 270 top
C791  10uF  [CC0805N]  32.58 71.66 180 top
C792  10uF  [CC0603N]  29.91 58.74 90 top
C793  0.01uF  [CC0402N]  34.09 79.54 180 top
C794  0.01uF  [CC0402N]  31 58.77 270 top
C795  0.01uF  [CC0402N]  27.77 78.83 270 top
C796  10uF  [CC0805N]  33.88 78.32 180 top
C797  10uF  [CC0603N]  23.68 57.2 270 top
C802  0.01uF  [CC0402N]  21.66 62.68 180 top
C803  10uF  [CC0603N]  20.65 58.45 270 top
C804  0.1u  [CC0402N]  164.75 42.02 270 top
C805  0.1u  [CC0402N]  159.22 48.22 270 top
C806  3900pF  [CC0402N]  244.36 83.76 90 bottom
C807  100nF  [CC0402N]  170.54 79.82 0 top
C808  100nF  [CC0402N]  175.47 81.53 225 top
C942  0.1u  [CC0402N]  125.36 87.94 0 bottom
C992  2.2uF  [CC0603N]  128.9 85.11 0 top
C2762  100nF  [CC0402N]  43.18 89.37 0 top
C2763  100nF  [CC0402N]  43.19 90.32 0 top
C2764  100nF  [CC0402N]  140.2 89.63 270 top
C2765  100nF  [CC0402N]  135.02 85.21 0 bottom
C2766  10uF  [CC0603N]  146.45 79.75 0 bottom
C2767  10uF  [CC0603N]  142.59 76.58 90 bottom
C2768  0.01uF  [CC0402N]  142.33 79.14 180 bottom
C2769  2.2uF  [CC0603N]  146.49 81.95 180 bottom
C2770  1uF  [CC0402N]  146.18 80.9 180 bottom
C2771  100nF  [CC0402N]  142.33 78.37 180 bottom
C2772  0.01uF  [CC0402N]  146.32 83.99 180 top
C2773  100nF  [CC0402N]  146.32 84.81 180 top
C2774  1uF  [CC0402N]  146.31 84.8 180 bottom
C2775  0.01uF  [CC0402N]  136.33 31.7 90 bottom
C2776  10uF  [CC0603N]  137.35 31.47 90 bottom
C2777  100nF  [CC0402N]  135.49 31.71 90 bottom
C2778  10uF  [CC0603N]  129.6 8.49 180 top
C2779  100nF  [CC0402N]  129.91 10.41 0 top
C2780  100nF  [CC0402N]  129.92 9.56 0 top
C2781  4.7uF  [CC0603N]  76.25 101.8 90 bottom
C2782  0.1u  [CC0402N]  75.26 101.32 90 bottom
C2783  0.1u  [CC0402N]  71.53 101.29 270 bottom
C2784  0.1u  [CC0402N]  78.17 98.75 0 bottom
C2785  1uF  [CC0402N]  70.88 99.15 270 bottom
C2786  0.1u  [CC0402N]  73.63 100.79 180 bottom
C2787  4.7uF  [CC0603N]  78.44 101.11 0 bottom
C2788  0.1u  [CC0402N]  77.83 96.36 180 bottom
C2789  2.2uF  [CC0603N]  78.11 95.36 0 bottom
C2790  4.7uF  [CC0603N]  78.44 99.75 0 bottom
C2791  4.7uF  [CC1206N]  94.39 98.08 90 bottom
C2833  10uF  [CC5750N]  98.46 95.78 90 bottom
C2834  470nF  [CC0402N]  129.71 86.71 90 top
C2835  10uF  [CC1210N]  120.64 88.79 0 bottom
C2836  10uF  [CC0805N]  96.57 57.57 180 bottom
C2837  10uF  [CC0805N]  96.56 59.21 0 bottom
C2838  0.1u  [CC0402N]  96.88 55.07 0 bottom
C2839  1uF  [CC0603N]  96.89 56.1 180 bottom
C2840  0.01uF  [CC0402N]  105.63 72.47 180 top
C2841  0.01uF  [CC0402N]  105.63 71.7 180 top
C2842  0.01uF  [CC0402N]  104.01 78.88 270 top
C2843  0.01uF  [CC0402N]  104.8 78.88 270 top
C2844  2.2uF  [CC0603N]  14.45 13.5 90 bottom
C2845  2.2uF  [CC0603N]  15.66 13.5 90 bottom
C2846  100nF  [CC0402N]  146.31 83.06 180 bottom
C2847  100nF  [CC0402N]  146.31 83.83 0 bottom
C2848  100nF  [CC0402N]  146.31 88.1 0 bottom
C2849  100nF  [CC0402N]  146.31 87.34 0 bottom
C2850  100nF  [CC0402N]  146.31 86.36 180 bottom
C2852  47UF  [CC0805N]  178.59 90.83 0 bottom
C2853  4.7uF  [CC0603N]  169.3 98.07 180 bottom
C2854  4.7uF  [CC0603N]  169.3 96.85 180 bottom
CN1  1782A1BX52A  [SMD-DDR4-50X820P-260N-AR]  205.99 17.89 0 top
CN3  SAF-0001BX-41-5N-0XX  [SMD-SATA-127P-22AN-L-KX]  100.47 62.94 270 top
CN5  213MAAA32  [SMD-M2PCIE-50X750P-75BN]  83.11 43.92 270 top
CN7  BS-06-A3A0J001  [SMD-BATTERY-2900P-2N]  71.96 85.15 0 bottom
CN9  CDZ-1.7-V10-2010  [TH-DCIN-540P-3N]  116.39 20.6 270 top
CN10  RJB-2X08X-XX-XX-XXX  [TH-RJ45-127P-8N]  95.04 20.6 90 top
CN14  1.25T-2-2PWB-T  [SMD-CN-125P-2WBN]  3.07 12.13 270 top
CN16  F2T20U-XXT3-E  [SMD-CN-50P-20N-H]  71.63 63.16 0 top
CN21  1.25T-2-2PWB-T  [SMD-CN-125P-2WBN]  247.52 26.52 90 top
CN22  SHNG04X-XX-XX-XXX  [TH-USB-250PX200P-4BN]  53.21 20.65 90 top
CN23  SHNG04X-XX-XX-XXX  [TH-USB-250PX200P-4BN]  68.93 20.65 90 top
CN24  CN-USB-9+4  [SMD-USB-100P-9AN]  35.85 95.1 180 top
CN25  WB1012US-04T5  [SMD-CN-100P-4N-V-CB]  167.15 16.19 90 top
CN26  M.2 SOCKET-1 SD/DP KEY E  [SMD-M2PCIE-50X750P-75AN]  128 22.61 90 top
CN35  WB1003UR-40XXB  [SMD-CN-100P-40AN-H]  135.37 99.5 180 bottom
CN36  CN-USB-9+4  [SMD-USB-100P-9AN]  8.95 95.1 180 top
CN37  MC38-1200X-XXD  [SMD-SD-250P-9N]  70.6 97.25 180 top
CN41  WB2012DR-02T2  [TH-CN-200P-2N-H]  92.3 93.69 180 bottom
CN42  WB1012US-02T5  [SMD-CN-100P-2N-V-CB]  57.99 7.82 0 top
CP1  220uF  [CCP7343N]  204.16 90.11 0 top
CP2  220uF  [CCP7343N]  200.49 94.83 90 bottom
CP3  220uF  [CCP7343N]  242.43 100.45 0 top
CP4  220uF  [CCP7343N]  241.68 90.13 0 top
CP7  330uF  [CCP7343N]  246.28 53.24 90 top
CP8  220uF  [CCP7343N]  178.67 91.82 0 bottom
CP9  330uF  [CCP7343N]  241.22 53.23 90 top
CP10  47UF  [CAE630W570HN]  216.58 101.89 0 bottom
CP13  330uF  [CCP7343N]  163.43 70.7 90 top
CP14  150UF  [CAE630W570HN]  7.66 62.49 180 top
CP15  150UF  [CAE630W570HN]  29.12 67.27 0 top
CP18  220uF  [CCP7343N]  242.43 95.28 0 top
CP20  330uF  [CCP7343N]  38.79 86.33 180 bottom
CP50  10UF  [THR-CPR50-630X1100N]  101.56 95.81 28.8 top
CP51  47UF  [CAE630W570HN]  168.94 97.49 180 bottom
CP52  220uF  [CCP7343N]  167.86 97.6 180 bottom
D1  BAT54WS-7-F  [SOD1713N]  172.46 45.24 90 top
D6  SK34L  [SOD5225N]  123.9 18.34 270 bottom
D7  AOZ8231  [SOD0806N]  9.88 91.52 0 top
D8  AOZ8231  [SOD0806N]  8.08 91.52 180 top
D17  1SS355TE17  [SOD2514N]  145.2 15.84 90 bottom
D18  1SS355TE17  [SOD2514N]  161.2 15.82 0 top
D19  AOZ8231  [SOD0806N]  64.51 19.62 270 top
D20  AOZ8231  [SOD0806N]  64.51 21.52 90 top
D21  AOZ8231  [SOD0806N]  48.92 19.58 270 top
D22  AOZ8231  [SOD0806N]  48.92 21.48 90 top
D23  SK34L  [SOD5225N]  18.44 80.72 90 top
D24  D_2PN  [SOT95P280-3N]  24.01 70.04 180 bottom
D25  D_2PN  [SOT95P280-3N]  23.61 65.04 90 bottom
D26  BAT54WS-7-F  [SOD1713N]  157.13 43.71 0 top
D28  SK34L  [SOD5225N]  7.81 79.03 90 top
D29  1SS355TE17  [SOD2514N]  147.19 15.84 90 bottom
D30  BAT54WS-7-F  [SOD1713N]  86.71 77.06 270 bottom
D31  BAT54WS-7-F  [SOD1713N]  88.43 77.06 270 bottom
D38  B2100  [SOD5336N]  106.7 94.02 180 bottom
D42  DFLS1100-7  [SOD2818N]  106.42 93.98 180 bottom
D2512  AOZ8231  [SOD0806N]  34.9 91.82 180 top
D2513  AOZ8231  [SOD0806N]  36.81 91.81 0 top
F2  1206L110//NANOSMDC110F  [F1206N]  22.25 85.98 180 bottom
F3  1206L110//NANOSMDC110F  [F1206N]  48.95 87.54 180 bottom
F4  1206L110//NANOSMDC110F  [F1206N]  41.8 18.78 0 top
F5  1206L110//NANOSMDC110F  [F1206N]  61.8 14.68 90 top
F8  3216FF-5A  [F1206N]  128.05 21.66 180 bottom
F9  0.5A  [F1206N]  118.57 84.48 270 bottom
FB2  120  [FB0805N]  78.65 55.08 90 bottom
FB3  120  [FB0805N]  72.08 51.58 270 bottom
FB4  120  [FB0805N]  133.03 20.28 180 bottom
FB5  120  [FB0805N]  133.03 21.91 180 bottom
FB6  47  [FB0603N]  79.91 22.14 0 top
FB7  120.0 ohm  [FB0603N]  11.69 27.69 90 bottom
FB8  120.0 ohm  [FB0603N]  6.53 10.07 180 bottom
FB9  120.0 ohm  [FB0603N]  5.34 28.21 180 bottom
FB10  120.0 ohm  [FB0603N]  22.92 15.52 90 bottom
FB11  120.0 ohm  [FB0603N]  8.61 26.69 90 bottom
FB12  120.0 ohm  [FB0603N]  9.87 26.68 90 bottom
FB13  180ohm  [FB0603N]  19.85 23.84 270 bottom
FB14  120  [FB0805N]  4.52 19.26 0 bottom
FB15  120  [FB0805N]  138.65 35.42 90 bottom
FB16  180  [FB0603N]  40.27 59.71 0 bottom
FB17  47  [FB0603N]  79.9 20.91 0 top
FB18  47  [FB0603N]  79.89 19.68 0 top
FB19  220  [FB0603N]  78.43 102.42 0 bottom
FB20  220  [FB0603N]  80.87 95.36 0 bottom
FB21  180  [FB0603N]  163.6 21.87 180 top
FB22  120.0 ohm  [FB0603N]  170.88 100.31 180 top
FB23  120.0 ohm  [FB0603N]  170.88 99.09 180 top
FB24  120.0 ohm  [FB0603N]  211.99 102.22 90 top
FB25  120.0 ohm  [FB0603N]  208.68 99.32 180 bottom
FB26  120.0 ohm  [FB0603N]  156.95 85.35 0 top
FB37  180  [FB0603N]  141.91 87.46 180 top
FB38  180  [FB0603N]  145.86 82.18 270 top
FB39  180  [FB0603N]  147.87 76.96 270 bottom
FB40  120  [FB0805N]  96.53 61.08 180 bottom
FB44  180  [FB0603N]  142 89.25 180 top
FB45  180  [FB0603N]  149.18 78.46 90 bottom
FIL1  330mA  [FIL_175P200X120-4L]  101.61 32.51 270 top
FIL2  330mA  [FIL_175P200X120-4L]  101.47 35.55 270 top
FIL3  330mA  [FIL_175P200X120-4L]  104.62 38.45 90 bottom
FIL4  330mA  [FIL_175P200X120-4L]  104.59 41.46 90 bottom
FIL5  330mA  [FIL_175P200X120-4L]  8.98 89.63 180 top
FIL6  330mA  [FIL_175P200X120-4L]  5.86 89.91 180 top
FIL7  330mA  [FIL_175P200X120-4L]  16.74 91.54 270 top
FIL9  330mA  [FIL_175P200X120-4L]  46.95 20.52 270 top
FIL10  330mA  [FIL_175P200X120-4L]  62.54 20.57 90 top
FIL14  330mA  [FIL_175P200X120-4L]  40.81 89.82 270 top
FIL15  330mA  [FIL_175P200X120-4L]  35.86 89.9 180 top
FIL16  330mA  [FIL_175P200X120-4L]  32.87 89.64 180 top
J2  PJ-358A  [TH-EARPHONE-330X400P-5N]  32.54 15.61 0 top
J3  PJ-358A  [TH-EARPHONE-330X400P-5N]  32.54 26.7 0 top
J5  CSI-1182-06XX-CN  [SMD-CN-100P-6N-H]  93.62 87.18 180 bottom
L3  2.2uH  [LC3030DL]  132.35 32.12 270 bottom
L4  2.2uH  [LC6666N]  9.07 70.96 270 top
L5  1.0uH  [LC6666N]  247.1 43.38 90 top
L9  2.2uH  [LC3030DL]  145.1 76.58 90 bottom
L12  1.5uH  [LC6666N]  163.6 61.44 90 top
L25  2.2uH  [LC4040L]  154.53 54.07 0 bottom
L26  2.2uH  [LC6666N]  20.35 71.73 90 top
L32  10uH  [LC6666N]  115.23 94.07 180 bottom
LED2  27-21/BHC-AN1P2/3C  [LED1706N]  104.63 7.45 180 top
LPM1  0.22UH  [LC115102N]  196.68 98.69 90 top
LPM8  0.22UH  [LC115102N]  230.47 98.46 270 top
LPM10  0.68UH  [LC5452N]  168.01 90.26 180 top
MARK1  MARK  [MARK-D100D250]  4.09 86.25 0 top
MARK2  MARK  [MARK-D100D250]  4.26 18.51 0 top
MARK3  MARK  [MARK-D100D250]  241.11 9.36 0 top
MARK4  MARK  [MARK-D100D250]  250.47 102.47 0 top
MARK5  MARK  [MARK-D100D250]  3.48 84.86 180 bottom
MARK6  MARK  [MARK-D100D250]  3.23 31.49 180 bottom
MARK7  MARK  [MARK-D100D250]  242.19 13.28 180 bottom
MARK8  MARK  [MARK-D100D250]  248.65 103.06 180 bottom
MH1  H  [MTG230H400]  206.4 102.6 0 top
MH4  -  [MTG380H500]  178.32 76.55 180 top
MH6  -  [MTG380H500]  235.32 76.55 180 top
MH7  H  [MTG230H500]  22.4 101.6 180 top
MH8  -  [MTG380H500]  178.32 56.55 180 top
MH9  H  [MTG250H500]  104.4 102.6 0 top
MH10  -  [MTG380H500]  235.32 56.55 180 top
MH22  H  [MTG340H580_TOP]  157.89 22.6 0 top
MH26  H  [MTG230H600]  42.4 12.1 180 bottom
MH27  H  [MTG250H500]  77.14 29.61 0 top
MH28  H  [MTG230H600]  105.88 14.1 180 bottom
MH29  H  [MTG340H580_TOP]  3.36 43.92 0 top
MH30  H  [MTG340H580_TOP]  108.41 76.44 0 top
MH31  H  [MTG340H580_TOP]  174.3 86.1 0 top
MH32  H  [MTG340H580_TOP]  161.15 37.45 0 top
MH33  H  [MTG340H580_TOP]  248.65 12.1 0 top
NOREF  -  [unnamed]  5 111.4 0 top
NOREF#2  -  [unnamed]  248.3 2.5 0 top
NOREF#3  -  [unnamed]  93.5 8.7 0 top
NOREF#4  -  [unnamed]  5 2.5 0 top
NOREF#5  -  [unnamed]  248.3 111.4 0 top
NOREF#6  -  [unnamed]  149.27 8.7 0 top
Q1  2N7002LT1  [SOT95P240-3N]  47.31 72.81 90 top
Q2  2N7002LT1  [SOT95P240-3N]  173.95 72.97 0 top
Q3  2N7002LT1  [SOT95P240-3N]  173.96 69.63 0 top
Q4  2N7002LT1  [SOT95P240-3N]  18.74 63.58 0 bottom
Q19  2N7002LT1  [SOT95P240-3N]  22.77 27.06 90 bottom
Q20  BSS138  [SOT95P280-3N]  21.98 31.95 90 bottom
Q21  BSS138  [SOT95P280-3N]  236.77 46.56 270 bottom
Q26  MMBT3904  [SOT95P230-3N]  242.87 67.96 180 top
Q30  SM4912TSK  [SOIC127P600-8N]  22.63 80.33 270 top
Q31  SM4912TSK  [SOIC127P600-8N]  11.98 79.42 270 top
Q36  2N7002LT1  [SOT95P240-3N]  18.76 10.92 180 bottom
Q43  APM3302QA  [SON65P330X330-8N]  26.9 58.14 180 top
Q45  2N7002LT1  [SOT95P240-3N]  27.48 60.3 180 bottom
Q46  2N7002LT1  [SOT95P240-3N]  27.25 64.52 180 bottom
Q47  DTC144EUA  [SOT65P210-3N]  161.94 18.59 90 top
Q48  2N7002LT1  [SOT95P240-3N]  132.07 87.48 180 top
Q49  sc-70  [SOT65P210-3N]  101.26 13.54 270 top
Q51  2N7002LT1  [SOT95P240-3N]  192.23 44.41 90 top
Q52  2N7002LT1  [SOT95P240-3N]  231.65 45.11 270 bottom
Q53  2N7002LT1  [SOT95P240-3N]  156.89 69.72 0 top
Q55  SM4912TSK  [SOIC127P600-8N]  162.36 53.06 90 top
Q56  2N7002LT1  [SOT95P240-3N]  150.19 17.9 0 bottom
Q57  2N7002LT1  [SOT95P240-3N]  150.19 14.46 180 bottom
Q58  AO4435  [SOIC127P600-8N]  143.95 22.02 0 bottom
Q59  BSS138  [SOT95P280-3N]  195.63 44.19 270 top
Q60  APM3302QA  [SON65P330X330-8N]  29.55 75.64 270 top
Q61  2N7002LT1  [SOT95P240-3N]  240.19 51.89 90 bottom
Q62  2N7002LT1  [SOT95P240-3N]  240.18 48.07 90 bottom
Q63  2N7002LT1  [SOT95P240-3N]  38.16 72.44 90 top
Q64  2N7002LT1  [SOT95P240-3N]  37.06 64.59 270 top
Q65  2N7002LT1  [SOT95P240-3N]  29.8 75.04 270 bottom
Q66  2N7002LT1  [SOT95P240-3N]  180.26 87.1 0 top
Q67  2N7002LT1  [SOT95P240-3N]  148.03 45.41 90 top
Q68  APM3302QA  [SON65P330X330-8N]  18.54 61.7 180 top
Q69  AON6428L  [SOIC127P605X520-8N]  180.23 100.03 180 top
Q70  AON6718L  [SOIC127P605X520-8N]  186.63 99.36 90 top
Q71  AON6428L  [SOIC127P605X520-8N]  213.72 97.75 180 top
Q72  AON6718L  [SOIC127P605X520-8N]  220.19 97.24 90 top
Q73  SM4912TSK  [SOIC127P600-8N]  161.78 88.19 90 top
Q74  2N7002LT1  [SOT95P240-3N]  47.31 68.15 90 top
Q76  BSS138  [SOT95P280-3N]  136.13 86.97 180 top
Q95  APM1105NUCT-TRG  [SOT229P990-3N]  106.99 86.56 90 bottom
R1  100k  [RC0402N]  174.23 52.86 0 bottom
R2  100k  [RC0402N]  174.22 53.65 0 bottom
R3  1M  [RC0402N]  207.15 82.01 180 top
R4  2.71K  [RC0402N]  209.83 82.38 270 top
R5  10M  [RC0402N]  188.33 46.06 180 bottom
R6  20K  [RC0402N]  177.77 46.14 90 bottom
R7  20K  [RC0402N]  179.18 46.14 90 bottom
R8  100k  [RC0402N]  191.85 46.78 90 bottom
R9  100k  [RC0402N]  190.95 47.61 90 top
R10  100k  [RC0402N]  191.16 49.31 90 bottom
R11  10k  [RC0402N]  174.19 50.84 0 bottom
R12  330K  [RC0402N]  174.19 49.99 180 bottom
R13  100k  [RC0402N]  167.92 48.75 0 top
R14  1k  [RC0402N]  183.16 76.02 90 top
R15  100k  [RC0402N]  187.46 81.21 270 top
R16  100k  [RC0402N]  195.25 48.52 180 bottom
R17  100k  [RC0402N]  195.25 49.34 0 bottom
R18  100k  [RC0402N]  190.35 49.31 90 bottom
R19  100k  [RC0402N]  172.88 50.33 270 bottom
R20  1k  [RC0402N]  230.94 83.96 0 top
R21  100k  [RC0402N]  174.23 52.07 0 bottom
R22  60.4  [RC0402N]  231.82 82.66 90 top
R23  10K  [RC0402N]  45.9 65.77 0 top
R24  0  [RC0402N]  190.95 49.39 90 top
R25  0  [RC0402N]  176 52.07 0 bottom
R26  100k  [RC0402N]  195.25 50.51 0 bottom
R27  1k  [RC0402N]  232.2 80.5 180 top
R28  1k  [RC0402N]  227.97 84.45 270 top
R29  -  [RC0402N]  227.2 84.45 270 top
R30  51  [RC0402N]  219.63 81.59 270 bottom
R31  51  [RC0402N]  221.49 84.14 270 bottom
R32  51  [RC0402N]  223.42 84.44 0 top
R33  51  [RC0402N]  223.22 83.44 90 bottom
R34  51  [RC0402N]  223.43 83.68 0 top
R35  51  [RC0402N]  221.24 82.36 90 bottom
R36  560  [RC0402N]  232.17 79.68 180 top
R37  100k  [RC0402N]  185.01 51.58 0 top
R38  100k  [RC0402N]  188.25 81.21 270 top
R39  51  [RC0402N]  219.8 83.39 270 bottom
R40  51  [RC0402N]  223.22 81.62 90 bottom
R41  -  [RC0402N]  181.2 48.03 270 top
R42  -  [RC0402N]  182.06 48.03 270 top
R43  -  [RC0402N]  221.92 70.71 180 bottom
R44  -  [RC0402N]  221.89 71.87 180 bottom
R45  1.8K  [RC0603N]  192.64 14.01 180 bottom
R46  2  [RC0402N]  227.17 45.34 0 bottom
R47  2  [RC0402N]  227.17 46.13 0 bottom
R48  25  [RC0402N]  227.17 43.77 0 bottom
R49  25  [RC0402N]  227.17 47.66 0 bottom
R50  0  [RC0402N]  212.05 61.08 0 bottom
R51  100  [RC0402N]  183.72 48.03 90 top
R52  80.6  [RC0402N]  189.32 46.95 90 top
R53  121  [RC0402N]  182.94 48.03 90 top
R54  10K  [RC0402N]  171.94 50.33 90 bottom
R55  2.2K  [RC0402N]  177.66 71.15 90 top
R56  2.2K  [RC0402N]  176.86 71.15 90 top
R57  2.2K  [RC0402N]  179.49 67.69 180 top
R58  2.2K  [RC0402N]  181.3 67.7 0 top
R59  24.9  [RC0402N]  224.81 82.66 180 top
R60  100k  [RC0402N]  192.31 71.64 0 bottom
R61  100k  [RC0402N]  179.78 72.93 270 top
R62  100k  [RC0402N]  180.56 72.93 270 top
R63  20K  [RC0402N]  189.62 83.16 270 top
R64  20K  [RC0402N]  190.4 83.16 270 top
R65  20K  [RC0402N]  191.18 83.16 270 top
R66  113  [RC0402N]  179.11 64.91 0 top
R67  100  [RC0402N]  183.99 76.02 270 top
R68  20K  [RC0402N]  188.85 83.16 270 top
R69  100k  [RC0402N]  197.03 48.9 90 top
R70  100k  [RC0402N]  21.66 63.46 180 top
R71  10K  [RC0402N]  17.26 61.51 0 bottom
R72  10K  [RC0402N]  13.05 70.44 0 bottom
R74  200  [RC0402N]  178.85 65.69 0 top
R75  1k  [RC0402N]  182.9 51.09 90 top
R77  20K  [RC0402N]  184.13 65.42 0 top
R80  100  [RC0402N]  195.29 71.97 270 bottom
R81  200  [RC0402N]  183.96 57.8 0 top
R82  2.2K  [RC0402N]  179.66 70.72 180 top
R83  2.2K  [RC0402N]  179.11 69.35 180 top
R84  10K  [RC0402N]  171.61 69.15 90 top
R85  10K  [RC0402N]  171.49 72.51 90 top
R86  249K  [RC0402N]  175.23 53.43 270 top
R87  1k  [RC0402N]  179.07 37.98 90 top
R90  10K  [RC0402N]  181.35 72.97 90 top
R91  4.7K  [RC0402N]  182.13 72.97 270 top
R92  100k  [RC0402N]  190.11 49.4 90 top
R93  10K  [RC0402N]  188.55 51.09 270 top
R94  10K  [RC0402N]  187.32 51.09 90 top
R95  100k  [RC0402N]  172.49 59.76 0 top
R97  20K  [RC0402N]  172.49 58.56 180 top
R98  100k  [RC0402N]  181.23 63.34 0 bottom
R99  100k  [RC0402N]  179.46 63.34 180 bottom
R101  20K  [RC0402N]  184.01 60.6 180 top
R102  0  [RC0402N]  44.22 63.52 180 bottom
R104  0  [RC0402N]  44.21 59.99 0 bottom
R105  47K  [RC0603N]  181.38 66.3 180 top
R106  1k  [RC0402N]  172.5 61.39 0 top
R107  1k  [RC0402N]  172.5 60.56 0 top
R108  1k  [RC0402N]  177.51 67.71 0 top
R109  1k  [RC0402N]  176.83 68.92 0 top
R110  1k  [RC0402N]  174.9 66.79 180 top
R111  1k  [RC0402N]  174.9 67.56 180 top
R112  47K  [RC0603N]  181.38 65.07 180 top
R113  100k  [RC0402N]  185.01 50.75 0 top
R114  100k  [RC0402N]  185.01 49.94 0 top
R115  100k  [RC0402N]  185.01 49.11 0 top
R116  100k  [RC0402N]  184.04 71.16 180 top
R117  100k  [RC0402N]  184.03 70.36 180 top
R118  100k  [RC0402N]  184.01 68.45 180 top
R119  0  [RC0603N]  171.45 63.06 180 bottom
R120  0  [RC0603N]  171.51 65.15 180 bottom
R121  0  [RC0603N]  174.88 62.91 180 top
R122  220  [RC0402N]  228.42 82.63 270 top
R123  0  [RC0603N]  198.66 83.28 90 bottom
R124  100  [RC0402N]  230.25 82.64 270 top
R125  56  [RC0402N]  229.2 82.63 90 top
R126  0  [RC0603N]  183.99 37.34 270 bottom
R127  0  [RC0603N]  185.21 37.34 270 bottom
R128  0  [RC0603N]  170.81 66.55 180 bottom
R129  0  [RC0603N]  167.88 60.52 270 bottom
R130  -  [RC0402N]  226.38 84.46 90 top
R131  0  [RC0603N]  174.88 64.14 180 top
R132  0  [RC0603N]  182.42 43.72 270 bottom
